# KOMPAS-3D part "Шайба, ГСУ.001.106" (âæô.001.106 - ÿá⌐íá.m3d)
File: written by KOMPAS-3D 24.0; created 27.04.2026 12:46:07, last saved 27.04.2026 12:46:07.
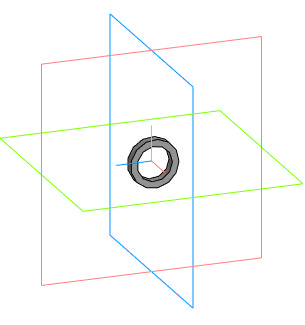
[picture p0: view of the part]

Document properties: Автор: User7; Полное имя файла: C:\Users\User7\Desktop\Двигатель мясорубки\ГСУ.001.106 - Шайба.m3d

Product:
- Part/product: Шайба  | designation ГСУ.001.106
    Масса: 0.000703

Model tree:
1. Эскиз:1
2. Элемент выдавливания:1
     Расстояние 1 = 2

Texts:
  ГСУ.001.106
